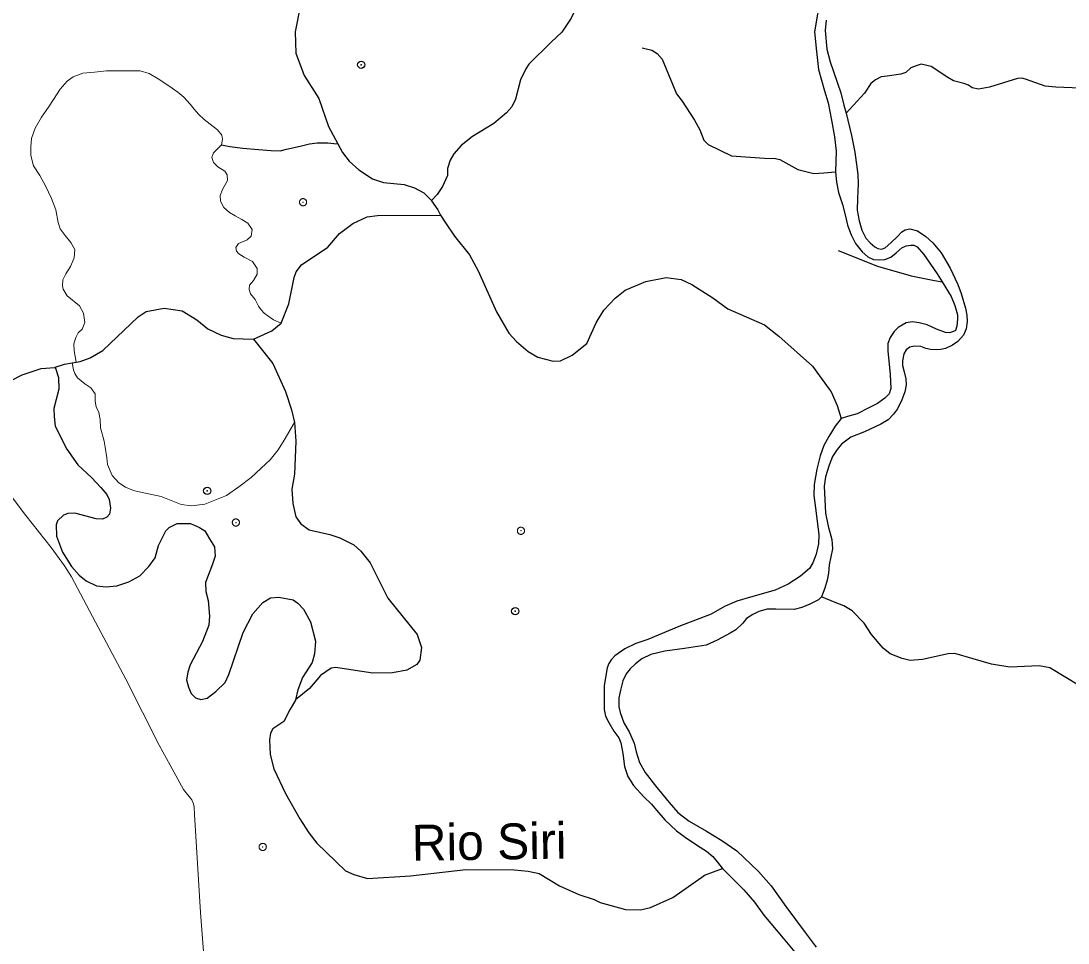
# Model space of a CAD drawing. Extents: x 267.7 to 296, y 7537.7 to 7565.8.
# Drawn here: x 275.825 to 278.742, y 7558.797 to 7561.365 of the extents above; entities that cross this region are included whole.
import ezdxf
from ezdxf.enums import TextEntityAlignment as Align

# ---------------------------------------------------------------- set-up
doc = ezdxf.new("R2010")
doc.units = 0
doc.header["$LTSCALE"] = 0.04
doc.header["$PDMODE"] = 32
doc.header["$PDSIZE"] = 0.02
doc.linetypes.add('SHORT_DASHED', pattern=[2.7, 1.5, -1.2])
for name, color, linetype, lineweight in [('1', 7, 'Continuous', 25), ('2', 7, 'Continuous', 25), ('21', 7, 'SHORT_DASHED', 13), ('7', 7, 'Continuous', 25)]:
    doc.layers.add(name, color=color, linetype=linetype, lineweight=lineweight)
doc.layers.add('54', color=7, linetype='Continuous')
doc.layers.add('61', color=7, linetype='Continuous')

msp = doc.modelspace()

# ---------------------------------------------------------------- linework, layer by layer
at = {"layer": '1', "lineweight": 13}
msp.add_lwpolyline([(276.3494, 7558.4938), (276.3404, 7558.6888), (276.3258, 7558.8824), (276.3086, 7559.1552), (276.3077, 7559.1752), (276.3058, 7559.1852), (276.3013, 7559.1961), (276.2786, 7559.2252), (276.2413, 7559.2925), (276.2104, 7559.3479), (276.1176, 7559.5316), (276.0331, 7559.6907), (275.9658, 7559.8171), (275.9467, 7559.848), (275.9094, 7559.8989), (275.8394, 7559.988), (275.7994, 7560.0407), (275.7521, 7560.1144), (275.7212, 7560.1535), (275.6703, 7560.2107), (275.6567, 7560.2271), (275.6444, 7560.2424)], dxfattribs=at)
at = {"layer": '2'}
for points in [[(278.0515, 7561.4356), (278.0527, 7561.4262), (278.0515, 7561.4131), (278.0438, 7561.3841), (278.0361, 7561.3349), (278.0373, 7561.3172), (278.0402, 7561.2881), (278.0473, 7561.2301), (278.0639, 7561.1703), (278.074, 7561.1371), (278.0835, 7561.0885), (278.0918, 7561.0423), (278.0965, 7561.0026), (278.0947, 7560.9444)], [(278.0682, 7561.3674), (278.0655, 7561.3387), (278.0698, 7561.2865), (278.0793, 7561.2508), (278.1092, 7561.165), (278.1177, 7561.1304), (278.124, 7561.1081)], [(278.124, 7561.1081), (278.1385, 7561.0462), (278.1486, 7560.9998), (278.1561, 7560.937), (278.1577, 7560.9109), (278.1555, 7560.8704), (278.1545, 7560.8379), (278.1598, 7560.8086), (278.1678, 7560.782), (278.1784, 7560.7596), (278.1907, 7560.7468), (278.2035, 7560.7361), (278.212, 7560.7308), (278.2221, 7560.7292), (278.2322, 7560.7329), (278.2488, 7560.7468), (278.2669, 7560.7644), (278.2791, 7560.7772), (278.2882, 7560.783), (278.3015, 7560.7862), (278.3228, 7560.7804), (278.3463, 7560.7649), (278.3654, 7560.7468), (278.3883, 7560.7191), (278.4139, 7560.6765), (278.4347, 7560.6307), (278.4448, 7560.6056), (278.4565, 7560.5651), (278.4603, 7560.5454), (278.4608, 7560.5278), (278.4581, 7560.5076), (278.4512, 7560.49), (278.4352, 7560.4719), (278.4198, 7560.4618), (278.4006, 7560.4532), (278.3878, 7560.4501), (278.3771, 7560.4495), (278.359, 7560.4501), (278.3463, 7560.4532), (278.3324, 7560.4586), (278.3132, 7560.4596), (278.301, 7560.4564), (278.2908, 7560.4495), (278.2845, 7560.4378), (278.2813, 7560.4186), (278.2813, 7560.4058), (278.2855, 7560.3877), (278.2903, 7560.3685), (278.2908, 7560.3515), (278.2871, 7560.3323), (278.2791, 7560.3094), (278.2674, 7560.2849), (278.2557, 7560.27), (278.2413, 7560.2545), (278.2205, 7560.2423), (278.1747, 7560.221), (278.1374, 7560.2055), (278.1113, 7560.1863), (278.0985, 7560.1714), (278.0863, 7560.1522), (278.0767, 7560.1283), (278.066, 7560.0952), (278.0628, 7560.0691), (278.0666, 7559.9946), (278.074, 7559.9578), (278.0841, 7559.9205), (278.0857, 7559.8949), (278.0767, 7559.8502), (278.0751, 7559.8273), (278.0714, 7559.8076), (278.0644, 7559.7852), (278.0554, 7559.761)], [(278.0947, 7560.9444), (278.0971, 7560.9156), (278.1024, 7560.8871), (278.1137, 7560.8534), (278.1226, 7560.8208), (278.1273, 7560.7965), (278.138, 7560.7693), (278.1504, 7560.745), (278.1688, 7560.7219), (278.1842, 7560.7077), (278.2002, 7560.7006), (278.2156, 7560.6994), (278.2321, 7560.7006), (278.2481, 7560.7071), (278.2635, 7560.7195), (278.2795, 7560.7331), (278.2908, 7560.7385), (278.3044, 7560.7408), (278.3121, 7560.7402), (278.3216, 7560.7355), (278.3405, 7560.7148), (278.3773, 7560.6603), (278.391, 7560.6382)], [(278.391, 7560.6382), (278.4163, 7560.5975), (278.427, 7560.5726), (278.4341, 7560.5466), (278.4341, 7560.5353), (278.4323, 7560.5146), (278.4288, 7560.5033), (278.4229, 7560.4998), (278.4116, 7560.4962), (278.4009, 7560.4974), (278.3755, 7560.5063), (278.3494, 7560.5187), (278.3269, 7560.5246), (278.3074, 7560.527), (278.2914, 7560.5246), (278.2689, 7560.5116), (278.2576, 7560.4998), (278.2469, 7560.4838), (278.2404, 7560.4666), (278.2398, 7560.4459), (278.2464, 7560.3807), (278.2481, 7560.341), (278.2434, 7560.3262), (278.2315, 7560.3144), (278.2114, 7560.2996), (278.1871, 7560.2877), (278.1545, 7560.2705), (278.1279, 7560.2634), (278.1098, 7560.2575)], [(278.1098, 7560.2575), (278.0935, 7560.2368), (278.0758, 7560.2078), (278.0615, 7560.1829), (278.0515, 7560.1539), (278.042, 7560.1171), (278.0349, 7560.0745), (278.0343, 7560.0437), (278.0402, 7559.9939), (278.0479, 7559.9335), (278.0467, 7559.9092), (278.0402, 7559.8802), (278.0313, 7559.8559), (278.0219, 7559.8405), (277.9964, 7559.8192), (277.962, 7559.7967), (277.9259, 7559.7801), (277.8572, 7559.76), (277.8193, 7559.7493), (277.7849, 7559.7345), (277.7482, 7559.7132), (277.6582, 7559.6782), (277.5717, 7559.6421), (277.5379, 7559.6314), (277.5071, 7559.616), (277.4799, 7559.5965), (277.4698, 7559.5858), (277.4627, 7559.5752), (277.458, 7559.5639), (277.4497, 7559.5141), (277.4497, 7559.4472), (277.4538, 7559.4294), (277.4627, 7559.4111), (277.4769, 7559.3874), (277.4905, 7559.3684), (277.4959, 7559.3548), (277.5018, 7559.3252), (277.5065, 7559.2885), (277.516, 7559.2612), (277.532, 7559.2358), (277.5604, 7559.2044), (277.5818, 7559.1836), (277.596, 7559.167), (277.6185, 7559.1404), (277.6511, 7559.1096), (277.6754, 7559.0918), (277.7097, 7559.0687), (277.7346, 7559.0533), (277.7524, 7559.0379), (277.7683, 7559.019), (277.7796, 7559.0044)], [(278.0554, 7559.761), (278.0474, 7559.7532), (278.0229, 7559.741), (278.0005, 7559.7314), (277.9792, 7559.7261), (277.928, 7559.7271), (277.9041, 7559.7266), (277.8812, 7559.7202), (277.8636, 7559.7117), (277.8465, 7559.7005), (277.8359, 7559.6877), (277.8167, 7559.6691), (277.8013, 7559.6605), (277.7645, 7559.6403), (277.7336, 7559.627), (277.6734, 7559.6174), (277.6191, 7559.6099), (277.5802, 7559.6009), (277.5551, 7559.5886), (277.537, 7559.5748), (277.5221, 7559.5609), (277.5114, 7559.5471), (277.5019, 7559.5273), (277.4955, 7559.5018), (277.4912, 7559.4799), (277.4907, 7559.4549), (277.4944, 7559.4389), (277.5045, 7559.4107), (277.5194, 7559.3851), (277.5333, 7559.3537), (277.5391, 7559.3292), (277.5487, 7559.2999), (277.5642, 7559.2722), (277.593, 7559.2354), (277.6308, 7559.1885), (277.6553, 7559.1603), (277.6867, 7559.1363), (277.7347, 7559.1086), (277.7778, 7559.083), (277.8194, 7559.0537), (277.8801, 7558.9962), (277.9147, 7558.9568), (277.9563, 7558.8992), (278.0096, 7558.8268), (278.0405, 7558.7858)], [(277.7796, 7559.0044), (277.8122, 7558.9722), (277.8394, 7558.9455), (277.8684, 7558.9106), (277.8945, 7558.875), (277.9484, 7558.8111), (277.981, 7558.772), (278.0142, 7558.737), (278.0373, 7558.7151), (278.058, 7558.7015), (278.0923, 7558.6861), (278.1314, 7558.6742), (278.1824, 7558.6582), (278.1898, 7558.655)]]:
    msp.add_lwpolyline(points, dxfattribs=at)
at = {"layer": '21'}
for points in [[(275.9792, 7560.4148), (275.9739, 7560.4464), (275.973, 7560.466), (275.9784, 7560.4838), (275.9846, 7560.4963), (275.9962, 7560.507), (276.0033, 7560.5248), (275.9998, 7560.5516), (275.9882, 7560.5712), (275.9543, 7560.5997), (275.9427, 7560.6176), (275.9409, 7560.6274), (275.9418, 7560.6443), (275.9507, 7560.6604), (275.9632, 7560.6809), (275.9739, 7560.7049), (275.9757, 7560.7281), (275.9641, 7560.7477), (275.9489, 7560.7674), (275.9347, 7560.7861), (275.9293, 7560.8039), (275.9222, 7560.8387), (275.9106, 7560.8708), (275.8936, 7560.9056), (275.8776, 7560.9341), (275.8607, 7560.9617), (275.8526, 7560.9903), (275.8526, 7561.0143), (275.8544, 7561.0375), (275.8651, 7561.0661), (275.8829, 7561.0973), (275.9017, 7561.1249), (275.9159, 7561.1463), (275.9347, 7561.1748), (275.9543, 7561.1971), (275.9712, 7561.2096), (275.998, 7561.2194), (276.0301, 7561.2221), (276.064, 7561.2257), (276.1032, 7561.2257), (276.1317, 7561.2257), (276.1576, 7561.2257), (276.1825, 7561.2185), (276.2075, 7561.2034), (276.2369, 7561.1838), (276.2628, 7561.1668), (276.2788, 7561.1526), (276.2967, 7561.1329), (276.3083, 7561.1196), (276.3199, 7561.1053), (276.3359, 7561.0901), (276.352, 7561.0777), (276.3725, 7561.0616), (276.385, 7561.0464), (276.3867, 7561.0357), (276.3841, 7561.0197)], [(276.3841, 7561.0197), (276.3751, 7561.0108), (276.3618, 7560.9974), (276.3573, 7560.9849), (276.3618, 7560.9707), (276.3734, 7560.9582), (276.393, 7560.9466), (276.4001, 7560.9359), (276.401, 7560.9207), (276.3957, 7560.9118), (276.3867, 7560.8958), (276.3805, 7560.8788), (276.3814, 7560.8628), (276.3903, 7560.8458), (276.4064, 7560.8316), (276.4224, 7560.8226), (276.4402, 7560.8119), (276.4572, 7560.8021), (276.4697, 7560.7843), (276.467, 7560.7656), (276.4554, 7560.7549), (276.4313, 7560.7451), (276.4242, 7560.7344), (276.426, 7560.7237), (276.4322, 7560.7165), (276.4474, 7560.7067), (276.4706, 7560.6951), (276.483, 7560.6755), (276.483, 7560.6595), (276.4732, 7560.6425), (276.4616, 7560.6291), (276.4607, 7560.6167), (276.4652, 7560.6051), (276.4777, 7560.589), (276.4875, 7560.5703), (276.4946, 7560.5605), (276.5027, 7560.5507), (276.5134, 7560.5435), (276.5285, 7560.5328), (276.5498, 7560.5235)], [(276.587, 7560.2466), (276.5586, 7560.1976), (276.5415, 7560.1702), (276.5193, 7560.1428), (276.5074, 7560.1318), (276.4662, 7560.0932), (276.432, 7560.0676), (276.3978, 7560.0436), (276.3379, 7560.0197), (276.3003, 7560.0145), (276.2712, 7560.018), (276.2155, 7560.0406), (276.1549, 7560.054), (276.1389, 7560.0576), (276.1166, 7560.0665), (276.0978, 7560.079), (276.0791, 7560.0995), (276.0666, 7560.1298), (276.0648, 7560.1485), (276.0595, 7560.178), (276.0568, 7560.1949), (276.047, 7560.2315), (276.0461, 7560.2555), (276.0426, 7560.2743), (276.0345, 7560.2903), (276.0319, 7560.3064), (276.0319, 7560.3269), (276.0203, 7560.3429), (276.0033, 7560.3545), (275.9828, 7560.3715), (275.9757, 7560.383), (275.9721, 7560.3937), (275.9684, 7560.413)]]:
    msp.add_lwpolyline(points, dxfattribs=at)
for p in [(276.6111, 7560.8601), (276.4241, 7559.9682), (277.2181, 7559.9452), (276.4989, 7559.0648)]:
    msp.add_point(p, dxfattribs=at)
at = {"layer": '54'}
for p in [(276.7732, 7561.2429), (276.3442, 7560.0565), (277.2022, 7559.7213)]:
    msp.add_point(p, dxfattribs=at)
at = {"layer": '7'}
for points in [[(276.5752, 7561.7649), (276.6507, 7561.7042), (276.6718, 7561.6815), (276.6842, 7561.6621), (276.6953, 7561.6202), (276.689, 7561.5726), (276.6786, 7561.5438), (276.6266, 7561.4636), (276.604, 7561.4099), (276.5893, 7561.3349), (276.5912, 7561.2748), (276.6147, 7561.213), (276.6549, 7561.1485), (276.6821, 7561.0705), (276.7077, 7561.0231)], [(277.4158, 7561.536), (277.4018, 7561.4623), (277.3582, 7561.3727), (277.3323, 7561.3334), (277.3019, 7561.3055), (277.2399, 7561.2441), (277.2317, 7561.2319), (277.2168, 7561.2013), (277.2026, 7561.1472), (277.1926, 7561.1261), (277.1781, 7561.1092), (277.1429, 7561.0793), (277.0834, 7561.043), (277.052, 7561.0179), (277.031, 7560.9947), (277.0209, 7560.9771), (277.0137, 7560.9544), (277.0134, 7560.9347), (276.9997, 7560.9042), (276.9843, 7560.8818), (276.9685, 7560.8647)], [(277.5555, 7561.2901), (277.5827, 7561.2831), (277.5971, 7561.2739), (277.6114, 7561.2585), (277.6402, 7561.1887), (277.6518, 7561.1623), (277.6669, 7561.1415), (277.7015, 7561.0882), (277.7161, 7561.0614), (277.728, 7561.0328), (277.7393, 7561.0209), (277.8046, 7560.9893), (277.8963, 7560.9831), (277.9272, 7560.9814), (277.9389, 7560.979), (277.9891, 7560.9509), (278.034, 7560.9399), (278.0621, 7560.9416), (278.0947, 7560.9444)], [(278.7754, 7561.1774), (278.7077, 7561.1805), (278.6779, 7561.1832), (278.624, 7561.2024), (278.6132, 7561.2051), (278.601, 7561.2044), (278.5231, 7561.1801), (278.4928, 7561.1748), (278.4747, 7561.1784), (278.4644, 7561.1856), (278.4517, 7561.1911), (278.4233, 7561.1979), (278.4076, 7561.207), (278.3611, 7561.2384), (278.333, 7561.2441), (278.3186, 7561.24), (278.3043, 7561.2339), (278.2899, 7561.2215), (278.2766, 7561.2164), (278.2386, 7561.2113), (278.2211, 7561.2092), (278.2057, 7561.201), (278.1931, 7561.1911), (278.177, 7561.1662), (278.1747, 7561.1637), (278.124, 7561.1081)], [(276.3841, 7561.0197), (276.4074, 7561.0152), (276.4432, 7561.0102), (276.4875, 7561.0069), (276.5225, 7561.0044), (276.5476, 7561.0035), (276.5651, 7561.0077), (276.6027, 7561.016), (276.6294, 7561.0227), (276.6503, 7561.0252), (276.6803, 7561.0252), (276.697, 7561.0236), (276.7077, 7561.0231)], [(276.7077, 7561.0231), (276.7211, 7560.9982), (276.7398, 7560.9747), (276.7669, 7560.95), (276.8044, 7560.9252), (276.8357, 7560.9149), (276.8927, 7560.9098), (276.9215, 7560.9006), (276.9474, 7560.8859), (276.9685, 7560.8647)], [(276.9685, 7560.8647), (276.9694, 7560.864), (276.9864, 7560.8387), (276.9944, 7560.8243)], [(276.5498, 7560.5235), (276.5716, 7560.577), (276.5861, 7560.6505), (276.5919, 7560.6661), (276.6068, 7560.6861), (276.6798, 7560.7352), (276.7131, 7560.7728), (276.7496, 7560.8009), (276.7895, 7560.8194), (276.8188, 7560.8231), (276.9944, 7560.8243)], [(276.9944, 7560.8243), (277.0078, 7560.8026), (277.0329, 7560.7658)], [(277.0329, 7560.7658), (277.0748, 7560.7138), (277.0992, 7560.669), (277.1497, 7560.5546), (277.1844, 7560.4956), (277.2057, 7560.472), (277.2379, 7560.4444), (277.2649, 7560.4289), (277.3076, 7560.4175), (277.3283, 7560.4182), (277.3611, 7560.4346), (277.4012, 7560.4663), (277.4278, 7560.5238), (277.4494, 7560.5598), (277.4804, 7560.5929), (277.5086, 7560.6149), (277.5664, 7560.6389), (277.6223, 7560.6504), (277.6647, 7560.6449), (277.6938, 7560.6308), (277.7523, 7560.5941), (277.7947, 7560.5631), (277.8968, 7560.5182), (277.9365, 7560.4869), (278.03, 7560.4034), (278.0771, 7560.3394), (278.0824, 7560.3322), (278.0987, 7560.2941), (278.1098, 7560.2575)], [(278.1021, 7560.7256), (278.2115, 7560.6822), (278.305, 7560.6555), (278.3701, 7560.6422), (278.391, 7560.6382)], [(275.9792, 7560.4148), (275.99, 7560.4166), (276.0186, 7560.4269), (276.0534, 7560.4471), (276.1523, 7560.5406), (276.1745, 7560.5559), (276.2244, 7560.5648), (276.2744, 7560.5573), (276.3157, 7560.5326), (276.3459, 7560.5076), (276.3828, 7560.4895), (276.4162, 7560.4806), (276.4725, 7560.4789), (276.4729, 7560.4791)], [(276.4729, 7560.4791), (276.5245, 7560.5017), (276.5498, 7560.5235)], [(276.4729, 7560.4791), (276.5272, 7560.4106), (276.5626, 7560.3328), (276.5792, 7560.2819), (276.587, 7560.2466)], [(275.7981, 7560.3637), (275.7983, 7560.364), (275.8283, 7560.3791), (275.8814, 7560.3968), (275.92, 7560.4002), (275.9209, 7560.4005)], [(275.9209, 7560.4005), (275.93, 7560.3724), (275.9309, 7560.3397), (275.9169, 7560.2857), (275.9179, 7560.2638), (275.9209, 7560.2362), (275.9536, 7560.1728), (275.9835, 7560.1284), (276.0215, 7560.0935), (276.0479, 7560.066), (276.0646, 7560.0463), (276.0708, 7560.0319), (276.0749, 7560.0077), (276.072, 7559.9916), (276.0646, 7559.9827), (276.0523, 7559.9775), (276.0352, 7559.978), (275.9758, 7559.9945), (275.9558, 7559.9934), (275.9438, 7559.989), (275.9273, 7559.9728), (275.9231, 7559.9615), (275.924, 7559.9303), (275.9412, 7559.8855), (275.9664, 7559.846), (275.9877, 7559.8219), (276.0072, 7559.8061), (276.0361, 7559.7923), (276.0632, 7559.7889), (276.0923, 7559.7915), (276.1262, 7559.8033), (276.1561, 7559.8198), (276.1818, 7559.8457), (276.1992, 7559.8702), (276.2087, 7559.9046), (276.2293, 7559.9446), (276.2383, 7559.9547), (276.2609, 7559.9651), (276.2977, 7559.9659), (276.3224, 7559.954), (276.3377, 7559.9447), (276.351, 7559.9231), (276.3644, 7559.9005), (276.3664, 7559.8749), (276.3591, 7559.8519), (276.3397, 7559.801), (276.3407, 7559.7763), (276.3469, 7559.7515), (276.3506, 7559.707), (276.3487, 7559.6825), (276.3315, 7559.6366), (276.297, 7559.572), (276.2903, 7559.5516), (276.2863, 7559.53), (276.2925, 7559.5095), (276.2997, 7559.492), (276.312, 7559.4797), (276.3264, 7559.4756), (276.3439, 7559.4794), (276.3679, 7559.4981), (276.3941, 7559.5228), (276.4045, 7559.5452), (276.4444, 7559.6618), (276.4714, 7559.7141), (276.4996, 7559.7451), (276.5207, 7559.758), (276.5438, 7559.76), (276.5838, 7559.7531), (276.597, 7559.744), (276.6126, 7559.727), (276.6322, 7559.6918), (276.6463, 7559.6376), (276.6431, 7559.6023), (276.637, 7559.5785), (276.6097, 7559.5362), (276.5963, 7559.5023), (276.5903, 7559.474)], [(275.9209, 7560.4005), (275.9465, 7560.4094), (275.9469, 7560.4095), (275.9684, 7560.413), (275.9792, 7560.4148)], [(276.587, 7560.2466), (276.5909, 7560.1947), (276.5871, 7560.1026), (276.5802, 7560.0606), (276.583, 7560.0213), (276.5909, 7559.9844), (276.6048, 7559.9643), (276.6279, 7559.9476), (276.686, 7559.9347), (276.7132, 7559.9251), (276.7522, 7559.9058), (276.7723, 7559.8883), (276.7979, 7559.8556), (276.8476, 7559.7575), (276.9289, 7559.6567), (276.9409, 7559.6197), (276.9366, 7559.5848), (276.9281, 7559.5731), (276.9004, 7559.5566), (276.8607, 7559.55), (276.8055, 7559.5486), (276.7018, 7559.5642), (276.6893, 7559.5622), (276.6598, 7559.5423), (276.6295, 7559.5059), (276.5903, 7559.474)], [(279.0197, 7559.3957), (278.986, 7559.4067), (278.8983, 7559.4211), (278.8297, 7559.4588), (278.7755, 7559.5121), (278.6911, 7559.5638), (278.6618, 7559.569), (278.5798, 7559.5655), (278.5291, 7559.5739), (278.4269, 7559.6037), (278.4084, 7559.6023), (278.3367, 7559.5866), (278.3027, 7559.584), (278.2797, 7559.5893), (278.2467, 7559.6021), (278.2269, 7559.6181), (278.1943, 7559.656), (278.1739, 7559.6878), (278.1408, 7559.7218), (278.1175, 7559.736), (278.0936, 7559.7456), (278.0554, 7559.761)], [(276.5903, 7559.474), (276.5899, 7559.4737), (276.5756, 7559.4484), (276.5573, 7559.414), (276.5273, 7559.3937), (276.5202, 7559.3819), (276.518, 7559.3627), (276.5198, 7559.3226), (276.5295, 7559.2822), (276.5624, 7559.2137), (276.6025, 7559.1431), (276.6271, 7559.104), (276.6497, 7559.0753), (276.7298, 7558.9987), (276.7523, 7558.9877), (276.7903, 7558.9773), (276.9106, 7558.9843), (277.0649, 7559.002), (277.1993, 7559.0013), (277.2383, 7558.9978), (277.2689, 7558.9905), (277.3257, 7558.9568), (277.3789, 7558.9323), (277.4218, 7558.9185), (277.4389, 7558.9105), (277.5094, 7558.891), (277.5514, 7558.89), (277.5793, 7558.896), (277.6411, 7558.9236), (277.7221, 7558.9809), (277.7296, 7558.9862), (277.7796, 7559.0044)]]:
    msp.add_lwpolyline(points, dxfattribs=at)

# ---------------------------------------------------------------- texts
at = {"layer": '61'}
msp.add_text('Rio Siri', height=0.1, rotation=0.862, dxfattribs=at).set_placement((277.1302, 7559.0293), align=Align.CENTER)

doc.saveas('drawing.dxf')
